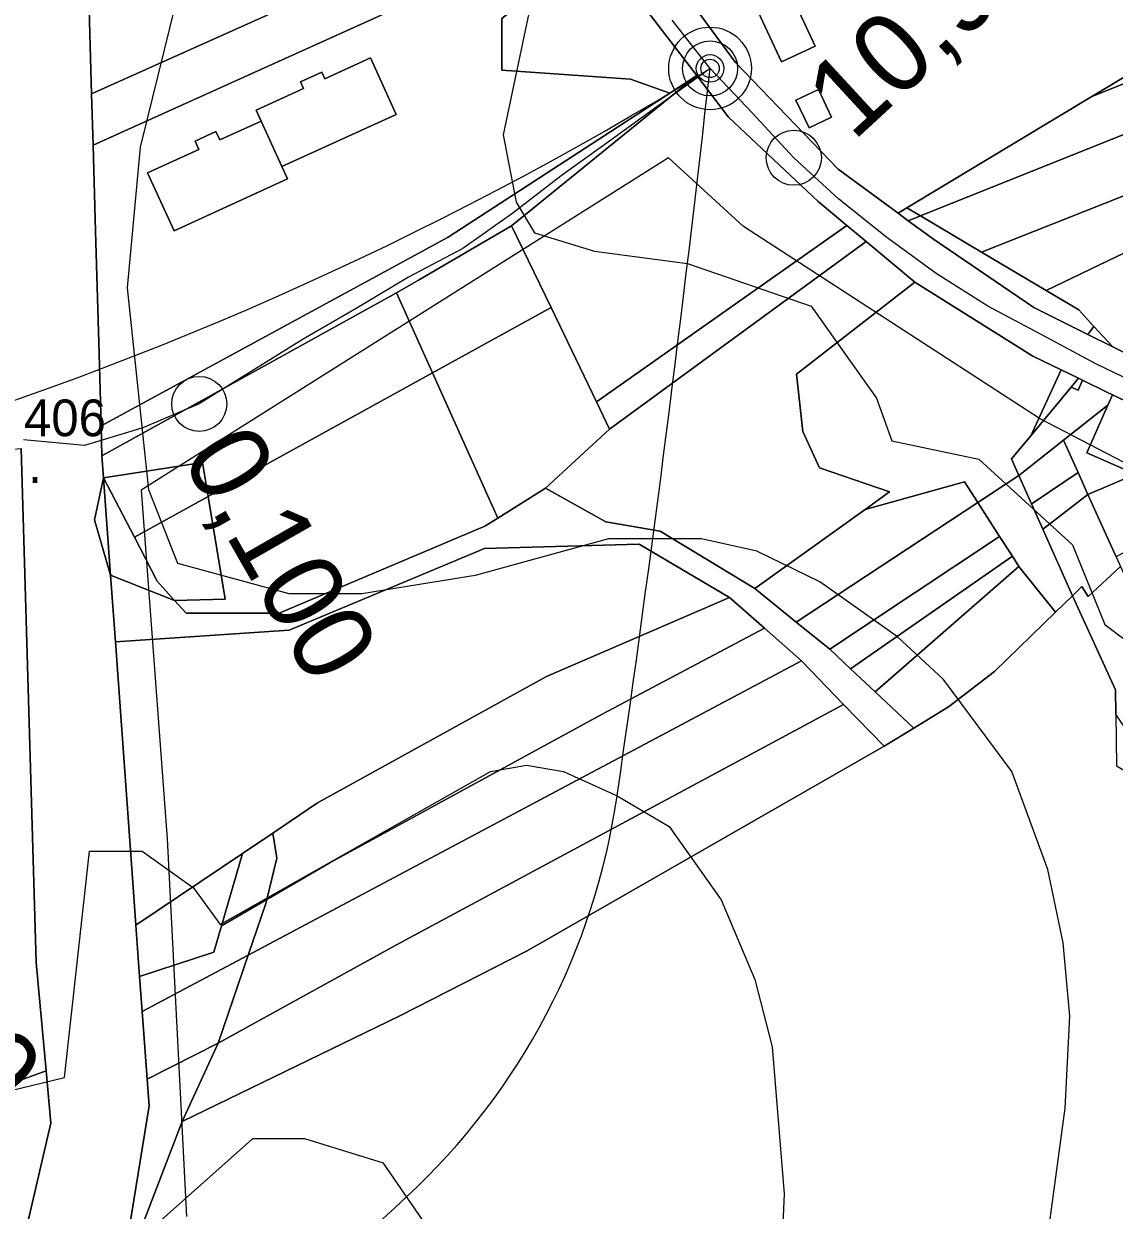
# Model space of a CAD drawing. Extents: x -510989 to -501240, y -1184665 to -1176089.
# Drawn here: x -509567.3 to -509389.1, y -1180046.7 to -1179852.8 of the extents above; entities that cross this region are included whole.
import ezdxf

# ---------------------------------------------------------------- set-up
doc = ezdxf.new("R2010")
doc.units = 0
for name, color, linetype in [('NAVRH_rozvodnice', 7, 'Continuous'), ('orna_puda', 7, 'Continuous'), ('ostatni_plocha_x_manipulacni_plocha', 7, 'Continuous'), ('ostatni_plocha_x_neplodna_puda', 7, 'Continuous'), ('ostatni_plocha_x_ostatni_komunikace', 7, 'Continuous'), ('ostatni_plocha_x_silnice', 7, 'Continuous'), ('ostatni_plocha_x_sportoviste_a_rekr_plocha', 7, 'Continuous'), ('STAV_systematicke_odvodneni', 7, 'Continuous'), ('trasovani_toku', 7, 'Continuous'), ('trvaly_travni_porost', 7, 'Continuous'), ('vodni_plocha_x_vodni_tok_v_koryte_umelem', 7, 'Continuous'), ('vrstevnice_01', 7, 'Continuous'), ('vrstevnice_02', 7, 'Continuous'), ('vrstevnice_05', 7, 'Continuous'), ('zahrada', 7, 'Continuous'), ('zastavena_plocha_a_nadvori', 7, 'Continuous')]:
    doc.layers.add(name, color=color, linetype=linetype)

msp = doc.modelspace()

# ---------------------------------------------------------------- linework, layer by layer
at = {"layer": 'NAVRH_rozvodnice'}
for radius in [4.5, 1.5]:
    msp.add_circle((-509455.12, -1179860.14), radius, dxfattribs=at)
for centre, radius, start, end in [((-509763.21, -1179360.62), 586.9, 270.37632, 301.6654), ((-513177.7, -1179444.68), 3745.7, 351.79888, 353.63187), ((-509579.99, -1179963.19), 110.81, 312.7974, 351.7989), ((-508952.13, -1180641.28), 813.32, 132.79738, 138.74782)]:
    msp.add_arc(centre, radius, start, end, dxfattribs=at)
at = {"layer": 'orna_puda'}
for points in [[(-509487.8, -1179833.66), (-509479.7, -1179830.12), (-509473.7, -1179839.94), (-509489.13, -1179851.97), (-509489.13, -1179860.43), (-509468.11, -1179861.9), (-509461.7, -1179864.18), (-509497.92, -1179887.72), (-509503.99, -1179891.02), (-509554.62, -1179918.53), (-509554.96, -1179906.78), (-509555.53, -1179886.74), (-509555.93, -1179872.66), (-509484.71, -1179840.51)], [(-509518.08, -1179861.83), (-509518.56, -1179860.77), (-509522.02, -1179862.34), (-509521.53, -1179863.4), (-509529.3, -1179866.94), (-509528.48, -1179868.75), (-509535.25, -1179871.83), (-509535.87, -1179870.46), (-509539.26, -1179872), (-509538.64, -1179873.37), (-509547.02, -1179877.2), (-509542.71, -1179886.65), (-509524.17, -1179878.2), (-509525.1, -1179876.15), (-509506.43, -1179867.65), (-509510.63, -1179858.43)], [(-509457.3, -1179861.32), (-509452.09, -1179868.11), (-509437.45, -1179881.9), (-509432.76, -1179885.8), (-509473.69, -1179914.62), (-509481.11, -1179899.22), (-509487.57, -1179885.83)], [(-509487.57, -1179885.83), (-509481.11, -1179899.22), (-509500.47, -1179909.89), (-509506.35, -1179896.78), (-509502.78, -1179894.71)], [(-509429.62, -1179888.4), (-509421.64, -1179895.04), (-509441.02, -1179910.07), (-509439.98, -1179919.47), (-509437.24, -1179925.37), (-509425.81, -1179929.33), (-509429.79, -1179932.19), (-509447.83, -1179945.13), (-509463.27, -1179935.74), (-509472.16, -1179934.22), (-509482, -1179928.7), (-509471.54, -1179919.06)], [(-509506.35, -1179896.78), (-509500.47, -1179909.89), (-509537.13, -1179930.1), (-509538.04, -1179924.55), (-509554.22, -1179927.05), (-509554.48, -1179923.44)], [(-509500.47, -1179909.89), (-509481.11, -1179899.22), (-509473.69, -1179914.62), (-509471.54, -1179919.06), (-509482, -1179928.7), (-509489.82, -1179933.64)], [(-509537.13, -1179930.1), (-509500.47, -1179909.89), (-509489.82, -1179933.64), (-509491.9, -1179934.95), (-509525.51, -1179949.13), (-509540.71, -1179949.13), (-509542.62, -1179947.05), (-509534.37, -1179946.86)], [(-509554.22, -1179927.05), (-509538.04, -1179924.55), (-509537.13, -1179930.1), (-509549.19, -1179936.75)], [(-509411.37, -1179931.05), (-509404.65, -1179926.63), (-509402.58, -1179931.28), (-509400.75, -1179935.42), (-509395.92, -1179946.29), (-509398.69, -1179948.99), (-509404.67, -1179941.49), (-509405.73, -1179939.84), (-509407.82, -1179936.59)], [(-509413.55, -1179927.66), (-509411.37, -1179931.05), (-509441.06, -1179950.59), (-509447.83, -1179945.13), (-509429.79, -1179932.19)], [(-509549.19, -1179936.75), (-509537.13, -1179930.1), (-509534.37, -1179946.86), (-509542.62, -1179947.05), (-509545.48, -1179943.91)], [(-509411.37, -1179931.05), (-509407.82, -1179936.59), (-509435.56, -1179955.02), (-509441.06, -1179950.59)], [(-509407.82, -1179936.59), (-509405.73, -1179939.84), (-509432.16, -1179958.22), (-509435.56, -1179955.02)], [(-509466.69, -1179937.84), (-509451.93, -1179946.57), (-509481.87, -1179959.48), (-509519.28, -1179980.15), (-509526.59, -1179985.08), (-509531.5, -1179988.39), (-509548.93, -1180000.14), (-509549.38, -1179993.92), (-509552.28, -1179953.85), (-509523.88, -1179951.91), (-509492, -1179938.56)], [(-509405.73, -1179939.84), (-509404.67, -1179941.49), (-509428.17, -1179961.97), (-509432.16, -1179958.22)], [(-509404.67, -1179941.49), (-509398.69, -1179948.99), (-509408.66, -1179958.69), (-509416.14, -1179964.47), (-509421.83, -1179967.93), (-509428.17, -1179961.97)], [(-509451.93, -1179946.57), (-509446.2, -1179951.61), (-509472.75, -1179965.65), (-509517.36, -1179990.01), (-509527.55, -1179995.92), (-509525.92, -1179989.17), (-509526.59, -1179985.08), (-509519.28, -1179980.15), (-509481.87, -1179959.48)], [(-509446.2, -1179951.61), (-509440.18, -1179956.91), (-509530.59, -1180005.01), (-509527.71, -1179996.59), (-509527.55, -1179995.92), (-509517.36, -1179990.01), (-509472.75, -1179965.65)], [(-509440.18, -1179956.91), (-509433.3, -1179964.04), (-509506.37, -1180003.34), (-509535.5, -1180019.37), (-509530.59, -1180005.01)], [(-509433.3, -1179964.04), (-509426.69, -1179970.89), (-509485.03, -1180004.33), (-509505.8, -1180014.94), (-509541.37, -1180032.19), (-509535.5, -1180019.37), (-509506.37, -1180003.34)]]:
    msp.add_lwpolyline(points, close=True, dxfattribs=at)
for points in [[(-509551.44, -1180058.44), (-509541.37, -1180032.19), (-509505.8, -1180014.94), (-509485.03, -1180004.33), (-509426.69, -1179970.89), (-509421.83, -1179967.93), (-509416.14, -1179964.47), (-509408.66, -1179958.69), (-509398.69, -1179948.99), (-509395.92, -1179946.29), (-509388.88, -1179961.65), (-509388.82, -1179965.62), (-509388.69, -1179974.07), (-509378.19, -1179980.22), (-509365.84, -1179987.46), (-509338.79, -1180003.3), (-509322.79, -1180012.68), (-509322.74, -1180012.71), (-509295.45, -1180028.39), (-509258.93, -1180049.38)], [(-509722.44, -1180081.65), (-509563.62, -1180023.92), (-509562.83, -1180032.49), (-509569.47, -1180061.07)]]:
    msp.add_lwpolyline(points, dxfattribs=at)
at = {"layer": 'ostatni_plocha_x_manipulacni_plocha'}
for points in [[(-509399.39, -1179759.66), (-509391.24, -1179775.51), (-509385.86, -1179785.98), (-509380.89, -1179795.66), (-509375.64, -1179805.88), (-509371.39, -1179814.14), (-509367.19, -1179822.32), (-509363.5, -1179829.51), (-509359.77, -1179836.76), (-509356.55, -1179843.03), (-509355.83, -1179844.44), (-509370.72, -1179855.06), (-509373.44, -1179857.05), (-509392.72, -1179864.7), (-509360.28, -1179845.17), (-509392.82, -1179776.12), (-509400.37, -1179760.1)], [(-509392.72, -1179864.7), (-509373.44, -1179857.05), (-509387.09, -1179866.99), (-509384.95, -1179869.92), (-509420.74, -1179884.22), (-509422.95, -1179882.91)], [(-509330.73, -1179871.11), (-509327.4, -1179867.35), (-509315.06, -1179878.28), (-509352.27, -1179892.87), (-509383.95, -1179908.3), (-509389.33, -1179905.62), (-509392.39, -1179902.31), (-509394.88, -1179899.6), (-509400.22, -1179896.42), (-509374.61, -1179884.12), (-509365.95, -1179896.02), (-509351.43, -1179888.3), (-509351.87, -1179880.37), (-509354.63, -1179876.66), (-509333.41, -1179868.74)], [(-509384.95, -1179869.92), (-509379.29, -1179877.7), (-509410.77, -1179890.15), (-509420.74, -1179884.22)], [(-509379.29, -1179877.7), (-509374.61, -1179884.12), (-509400.22, -1179896.42), (-509410.77, -1179890.15)], [(-509424.41, -1179883.79), (-509422.95, -1179882.91), (-509420.74, -1179884.22), (-509422.73, -1179885.02)], [(-509420.74, -1179884.22), (-509410.77, -1179890.15), (-509400.22, -1179896.42), (-509394.88, -1179899.6), (-509392.39, -1179902.31), (-509393.41, -1179903.59), (-509402.2, -1179899.21), (-509418.62, -1179888.05), (-509422.73, -1179885.02)], [(-509393.41, -1179903.59), (-509392.39, -1179902.31), (-509389.33, -1179905.62)], [(-509397.74, -1179909.39), (-509394.91, -1179910.77), (-509396.12, -1179912.23), (-509402.72, -1179920.16)], [(-509394.98, -1179912.73), (-509394.25, -1179911.09), (-509390.29, -1179913.01), (-509389.38, -1179913.45), (-509390.13, -1179915.15), (-509397.39, -1179920.89), (-509404.45, -1179926.47), (-509404.65, -1179926.63), (-509405.85, -1179923.93), (-509402.72, -1179920.16), (-509396.12, -1179912.23)], [(-509394.91, -1179910.77), (-509394.25, -1179911.09), (-509394.98, -1179912.73), (-509396.12, -1179912.23)], [(-509397.39, -1179920.89), (-509390.13, -1179915.15), (-509393.58, -1179922.92), (-509385.61, -1179926.45), (-509393.37, -1179929.75), (-509395, -1179926.15)], [(-509389.38, -1179913.45), (-509387.29, -1179914.47), (-509378.36, -1179918.79), (-509376.83, -1179919.53), (-509378.56, -1179923.45), (-509380.85, -1179924.42), (-509382.97, -1179925.32), (-509385.61, -1179926.45), (-509393.58, -1179922.92), (-509390.13, -1179915.15)], [(-509397.39, -1179920.89), (-509395, -1179926.15), (-509402.01, -1179930.89), (-509402.58, -1179931.28), (-509404.65, -1179926.63), (-509404.45, -1179926.47)], [(-509376.83, -1179919.53), (-509373.43, -1179921.18), (-509373.34, -1179921.23), (-509363.35, -1179925.82), (-509388.75, -1179939.93), (-509393.37, -1179929.75), (-509385.61, -1179926.45), (-509380.82, -1179928.56), (-509378.56, -1179923.45)], [(-509395, -1179926.15), (-509393.37, -1179929.75), (-509399.88, -1179934.75), (-509400.75, -1179935.42), (-509402.58, -1179931.28), (-509402.01, -1179930.89)], [(-509393.37, -1179929.75), (-509388.75, -1179939.93), (-509388.04, -1179941.5), (-509393.33, -1179946.42), (-509394.35, -1179944.76), (-509395.92, -1179946.29), (-509400.75, -1179935.42), (-509399.88, -1179934.75)], [(-509394.35, -1179944.76), (-509393.33, -1179946.42), (-509388.04, -1179941.5), (-509384.44, -1179949.43), (-509381.09, -1179956.83), (-509380.38, -1179958.4), (-509364.58, -1179957.55), (-509334.17, -1179955.93), (-509332.25, -1179957.57), (-509357.74, -1179964.06), (-509385.2, -1179971.06), (-509388.82, -1179965.62), (-509388.88, -1179961.65), (-509395.92, -1179946.29)]]:
    msp.add_lwpolyline(points, close=True, dxfattribs=at)
at = {"layer": 'ostatni_plocha_x_neplodna_puda'}
for points in [[(-509473.7, -1179839.94), (-509457.3, -1179861.32), (-509461.7, -1179864.18), (-509468.11, -1179861.9), (-509489.13, -1179860.43), (-509489.13, -1179851.97)], [(-509461.7, -1179864.18), (-509457.3, -1179861.32), (-509487.57, -1179885.83), (-509502.78, -1179894.71), (-509506.35, -1179896.78), (-509554.48, -1179923.44), (-509554.62, -1179918.53), (-509503.99, -1179891.02), (-509497.92, -1179887.72)], [(-509432.76, -1179885.8), (-509429.62, -1179888.4), (-509471.54, -1179919.06), (-509473.69, -1179914.62)], [(-509547.11, -1180025.3), (-509535.5, -1180019.37), (-509541.37, -1180032.19), (-509551.44, -1180058.44), (-509546.79, -1180029.63)]]:
    msp.add_lwpolyline(points, close=True, dxfattribs=at)
at = {"layer": 'ostatni_plocha_x_ostatni_komunikace'}
for points in [[(-509494.94, -1179836.77), (-509487.8, -1179833.66), (-509484.71, -1179840.51), (-509555.93, -1179872.66), (-509556.17, -1179864.3), (-509508.13, -1179842.7), (-509495.19, -1179836.88)], [(-509549.19, -1179936.75), (-509545.48, -1179943.91), (-509542.62, -1179947.05), (-509553.07, -1179942.93), (-509554.22, -1179927.05)], [(-509489.82, -1179933.64), (-509482, -1179928.7), (-509472.16, -1179934.22), (-509463.27, -1179935.74), (-509447.83, -1179945.13), (-509441.06, -1179950.59), (-509435.56, -1179955.02), (-509432.16, -1179958.22), (-509428.17, -1179961.97), (-509421.83, -1179967.93), (-509426.69, -1179970.89), (-509433.3, -1179964.04), (-509440.18, -1179956.91), (-509446.2, -1179951.61), (-509451.93, -1179946.57), (-509466.69, -1179937.84), (-509492, -1179938.56), (-509523.88, -1179951.91), (-509552.28, -1179953.85), (-509552.6, -1179949.46), (-509553.07, -1179942.93), (-509542.62, -1179947.05), (-509540.71, -1179949.13), (-509525.51, -1179949.13), (-509491.9, -1179934.95)]]:
    msp.add_lwpolyline(points, close=True, dxfattribs=at)
at = {"layer": 'ostatni_plocha_x_silnice'}
for points in [[(-509556.69, -1179846.46), (-509556.17, -1179864.3), (-509555.93, -1179872.66), (-509555.53, -1179886.74), (-509554.96, -1179906.78), (-509554.62, -1179918.53), (-509554.48, -1179923.44), (-509554.22, -1179927.05), (-509555.72, -1179933.87), (-509553.07, -1179942.93), (-509552.6, -1179949.46), (-509552.28, -1179953.85), (-509549.38, -1179993.92), (-509548.93, -1180000.14), (-509548.33, -1180008.48), (-509547.91, -1180014.23), (-509547.11, -1180025.3), (-509546.79, -1180029.63), (-509551.44, -1180058.44)], [(-509569.47, -1180061.07), (-509562.83, -1180032.49), (-509563.62, -1180023.92), (-509565.24, -1180006.24), (-509567.68, -1179922.21)]]:
    msp.add_lwpolyline(points, dxfattribs=at)
msp.add_lwpolyline([(-509555.72, -1179933.87), (-509554.22, -1179927.05), (-509553.07, -1179942.93)], close=True, dxfattribs=at)
at = {"layer": 'ostatni_plocha_x_sportoviste_a_rekr_plocha'}
for points in [[(-509414.56, -1179729.99), (-509412.04, -1179735.34), (-509407.79, -1179744.35), (-509400.37, -1179760.1), (-509392.82, -1179776.12), (-509360.28, -1179845.17), (-509392.72, -1179864.7), (-509422.95, -1179882.91), (-509424.41, -1179883.79), (-509434.17, -1179876.61), (-509450.96, -1179859.19), (-509460.71, -1179845.86), (-509459.71, -1179845.32), (-509451.84, -1179841.02), (-509443.46, -1179859.06), (-509437.94, -1179856.49), (-509446.31, -1179838.46), (-509464.68, -1179787.36), (-509473.71, -1179744.29), (-509437.87, -1179732.2), (-509434.32, -1179735.89), (-509415.75, -1179727.46)], [(-509437.43, -1179863.59), (-509441.09, -1179865.34), (-509438.95, -1179869.84), (-509435.29, -1179868.1)]]:
    msp.add_lwpolyline(points, close=True, dxfattribs=at)
at = {"layer": 'STAV_systematicke_odvodneni'}
for p, q in [((-509461.92, -1179874.77), (-509548.1, -1179929.05)), ((-509449.68, -1179885.95), (-509461.92, -1179874.77)), ((-509401.27, -1179917.35), (-509449.68, -1179885.95)), ((-509260.83, -1179990.26), (-509401.27, -1179917.35)), ((-509548.1, -1179929.05), (-509543.84, -1179986)), ((-509543.84, -1179986), (-509540.65, -1180047.74))]:
    msp.add_line(p, q, dxfattribs=at)
at = {"layer": 'trasovani_toku'}
for p, q in [((-509455.12, -1179860.14), (-509461.3, -1179852.28)), ((-509455.12, -1179860.14), (-509463.23, -1179865.98)), ((-509448.26, -1179867.41), (-509455.12, -1179860.14)), ((-509463.23, -1179865.98), (-509471.34, -1179871.84)), ((-509441.44, -1179874.73), (-509448.26, -1179867.41)), ((-509471.34, -1179871.84), (-509479.45, -1179877.69)), ((-509434.07, -1179881.49), (-509441.44, -1179874.73)), ((-509479.45, -1179877.69), (-509487.36, -1179883.81)), ((-509426.26, -1179887.74), (-509434.07, -1179881.49)), ((-509487.36, -1179883.81), (-509495.54, -1179889.56)), ((-509418.19, -1179893.64), (-509426.26, -1179887.74)), ((-509495.54, -1179889.56), (-509504.38, -1179894.22)), ((-509409.73, -1179898.98), (-509418.19, -1179893.64)), ((-509504.38, -1179894.22), (-509512.96, -1179899.37)), ((-509512.96, -1179899.37), (-509521.62, -1179904.36)), ((-509400.91, -1179903.68), (-509409.73, -1179898.98)), ((-509521.62, -1179904.36), (-509530.11, -1179909.65)), ((-509392.08, -1179908.38), (-509400.91, -1179903.68)), ((-509383.1, -1179912.78), (-509392.08, -1179908.38)), ((-509530.11, -1179909.65), (-509538.59, -1179914.95)), ((-509538.59, -1179914.95), (-509547.79, -1179918.88)), ((-509547.79, -1179918.88), (-509557.36, -1179921.77)), ((-509557.36, -1179921.77), (-509567.31, -1179920.81))]:
    msp.add_line(p, q, dxfattribs=at)
for centre, radius in [((-509455.12, -1179860.14), 6.75), ((-509455.12, -1179860.14), 2.25), ((-509441.44, -1179874.73), 4.5), ((-509538.59, -1179914.95), 4.5)]:
    msp.add_circle(centre, radius, dxfattribs=at)
at = {"layer": 'trvaly_travni_porost'}
for points in [[(-509421.64, -1179895.04), (-509402.4, -1179907.13), (-509397.74, -1179909.39), (-509402.72, -1179920.16), (-509405.85, -1179923.93), (-509404.65, -1179926.63), (-509411.37, -1179931.05), (-509413.55, -1179927.66), (-509429.79, -1179932.19), (-509425.81, -1179929.33), (-509437.24, -1179925.37), (-509439.98, -1179919.47), (-509441.02, -1179910.07)], [(-509531.5, -1179988.39), (-509526.59, -1179985.08), (-509525.92, -1179989.17), (-509527.55, -1179995.92), (-509534.94, -1180000.2)], [(-509548.93, -1180000.14), (-509531.5, -1179988.39), (-509534.94, -1180000.2), (-509536.21, -1180004.55), (-509548.33, -1180008.48)], [(-509527.71, -1179996.59), (-509530.59, -1180005.01), (-509547.91, -1180014.23), (-509548.33, -1180008.48), (-509536.21, -1180004.55), (-509534.94, -1180000.2), (-509527.55, -1179995.92)], [(-509530.59, -1180005.01), (-509535.5, -1180019.37), (-509547.11, -1180025.3), (-509547.91, -1180014.23)]]:
    msp.add_lwpolyline(points, close=True, dxfattribs=at)
msp.add_lwpolyline([(-509967.35, -1180059.23), (-509800.89, -1180057.29), (-509791.69, -1180055.81), (-509786.94, -1180054.7), (-509694.28, -1180014.14), (-509603.1, -1179974.24), (-509580.47, -1179962.08), (-509571.85, -1179922.59), (-509567.68, -1179922.21), (-509565.24, -1180006.24), (-509563.62, -1180023.92), (-509722.44, -1180081.65), (-509754.45, -1180090.32), (-509816.6, -1180104.43), (-509819.08, -1180096.5), (-509827.86, -1180088.44), (-509830.07, -1180080.34), (-509842.17, -1180079.77), (-509878.93, -1180085.53), (-509891.98, -1180088.58), (-509953.4, -1180109.7)], dxfattribs=at)
at = {"layer": 'vodni_plocha_x_vodni_tok_v_koryte_umelem'}
for points in [[(-509501.54, -1179743.91), (-509486.95, -1179796.31), (-509480.74, -1179811.12), (-509470.06, -1179833.07), (-509460.71, -1179845.86), (-509450.96, -1179859.19), (-509434.17, -1179876.61), (-509424.41, -1179883.79), (-509422.73, -1179885.02), (-509418.62, -1179888.05), (-509402.2, -1179899.21), (-509393.41, -1179903.59), (-509389.33, -1179905.62), (-509383.95, -1179908.3)], [(-509387.29, -1179914.47), (-509389.38, -1179913.45), (-509390.29, -1179913.01), (-509394.25, -1179911.09), (-509394.91, -1179910.77), (-509397.74, -1179909.39), (-509402.4, -1179907.13), (-509421.64, -1179895.04), (-509429.62, -1179888.4), (-509432.76, -1179885.8), (-509437.45, -1179881.9), (-509452.09, -1179868.11), (-509457.3, -1179861.32), (-509473.7, -1179839.94), (-509479.7, -1179830.12), (-509486.47, -1179815.92), (-509492.75, -1179799.76), (-509507.62, -1179753.22), (-509509.72, -1179746.36)]]:
    msp.add_lwpolyline(points, dxfattribs=at)
at = {"layer": 'vrstevnice_01'}
for points in [[(-509482.81, -1179842), (-509488.91, -1179871), (-509486.81, -1179882), (-509483.81, -1179887), (-509474, -1179890), (-509458.81, -1179892), (-509438.59, -1179899), (-509427.91, -1179914), (-509425.41, -1179921), (-509411.19, -1179924), (-509395.91, -1179938), (-509390.59, -1179951), (-509377.31, -1179961)], [(-509617.5, -1180052), (-509589.59, -1180034), (-509573, -1180028), (-509560.59, -1180025), (-509556.5, -1179988), (-509547.91, -1179988), (-509539.5, -1179994), (-509535.19, -1180000), (-509491, -1179975), (-509485.09, -1179974), (-509479.09, -1179975), (-509470.31, -1179979), (-509461.81, -1179984), (-509453.31, -1179996), (-509447.81, -1180009), (-509445, -1180020), (-509443, -1180044), (-509444.5, -1180077)]]:
    msp.add_lwpolyline(points, dxfattribs=at)
at = {"layer": 'vrstevnice_02'}
for points in [[(-509401.31, -1180061), (-509397.09, -1180030), (-509396.31, -1180015), (-509397.41, -1180003), (-509399.91, -1179991), (-509405.81, -1179975), (-509417, -1179960), (-509424.5, -1179953), (-509437.19, -1179944), (-509447.5, -1179939), (-509456.5, -1179937), (-509471.69, -1179937), (-509493.5, -1179943), (-509512, -1179946), (-509523.91, -1179946), (-509542.09, -1179941), (-509546.81, -1179929), (-509550.31, -1179896), (-509548.19, -1179873), (-509532.69, -1179810)], [(-509500.91, -1180050), (-509508.5, -1180039), (-509521.31, -1180035), (-509529.91, -1180035), (-509547.81, -1180051)]]:
    msp.add_lwpolyline(points, dxfattribs=at)
at = {"layer": 'zahrada'}
msp.add_lwpolyline([(-509533.1, -1179820.45), (-509535.1, -1179821.32), (-509546.87, -1179825.05), (-509524.26, -1179814.58), (-509508.13, -1179842.7), (-509556.17, -1179864.3), (-509556.69, -1179846.46), (-509527.34, -1179833.86)], close=True, dxfattribs=at)
at = {"layer": 'zastavena_plocha_a_nadvori'}
for points in [[(-509451.84, -1179841.02), (-509446.31, -1179838.46), (-509437.94, -1179856.49), (-509443.46, -1179859.06)], [(-509518.08, -1179861.83), (-509510.63, -1179858.43), (-509506.43, -1179867.65), (-509525.1, -1179876.15), (-509528.48, -1179868.75), (-509529.3, -1179866.94), (-509521.53, -1179863.4), (-509522.02, -1179862.34), (-509518.56, -1179860.77)], [(-509437.43, -1179863.59), (-509435.29, -1179868.1), (-509438.95, -1179869.84), (-509441.09, -1179865.34)], [(-509535.25, -1179871.83), (-509528.48, -1179868.75), (-509525.1, -1179876.15), (-509524.17, -1179878.2), (-509542.71, -1179886.65), (-509547.02, -1179877.2), (-509538.64, -1179873.37), (-509539.26, -1179872), (-509535.87, -1179870.46)]]:
    msp.add_lwpolyline(points, close=True, dxfattribs=at)

# ---------------------------------------------------------------- texts
at = {"layer": 'trasovani_toku'}
for s, rotation, p in [('10,900', 42.6836, (-509431.76, -1179872.2)), ('0,100', 299.7345, (-509541.63, -1179923.63)), ('0,200', 308.2221, (-509600.44, -1179997.05))]:
    msp.add_text(s, height=13, rotation=rotation, dxfattribs=at).set_placement(p)
at = {"layer": 'vrstevnice_05'}
for s, p in [('406', (-509567.22, -1179920.23)), ('.', (-509566.53, -1179927.85))]:
    msp.add_text(s, height=6, dxfattribs=at).set_placement(p)

doc.saveas('drawing.dxf')
